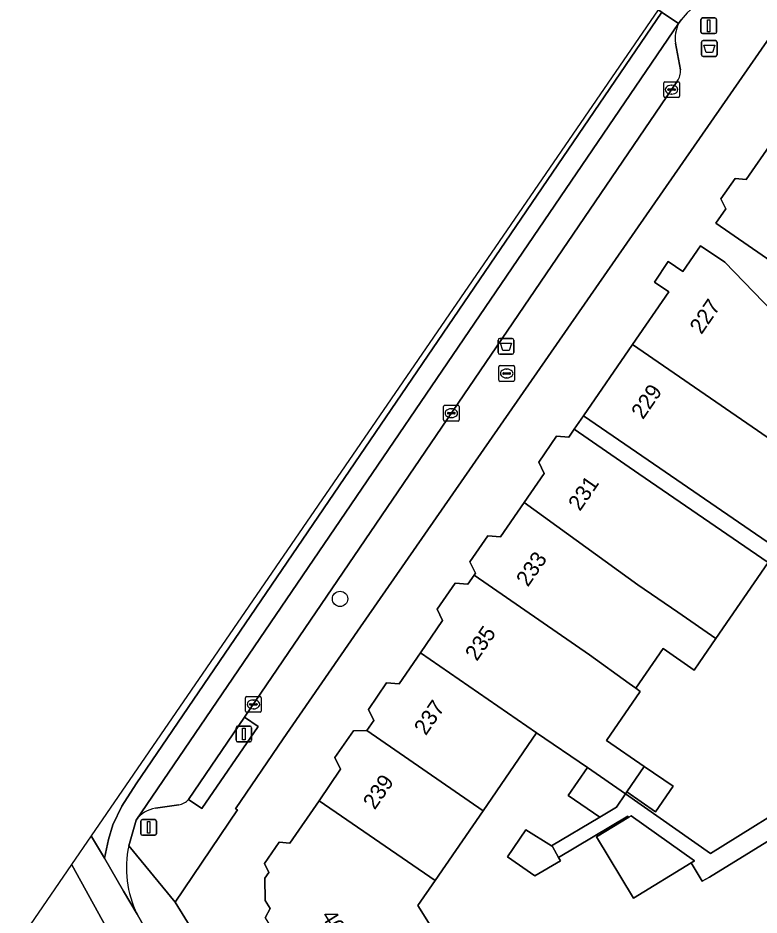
# Model space of a CAD drawing. Extents: x 160023 to 161302, y 384750 to 385707.
# Drawn here: x 160022.6 to 160069.8, y 385314.1 to 385371.2 of the extents above; entities that cross this region are included whole.
import ezdxf

# ---------------------------------------------------------------- set-up
doc = ezdxf.new("R2010")
doc.units = 0
for name, color, linetype in [('IMGEO_Afvalbak', 7, 'Continuous'), ('IMGEO_Boom', 7, 'Continuous'), ('IMGEO_Brandkraan', 7, 'Continuous'), ('IMGEO_Erf', 7, 'Continuous'), ('IMGEO_Fietspad_gesloten', 7, 'Continuous'), ('IMGEO_Kolk', 7, 'Continuous'), ('IMGEO_Lichtmast', 7, 'Continuous'), ('IMGEO_Pand', 7, 'Continuous'), ('IMGEO_Pand_nummerreeks', 7, 'Continuous'), ('IMGEO_Parkeervlak_open', 7, 'Continuous'), ('IMGEO_Rijbaan_lokaal_gesloten', 7, 'Continuous'), ('IMGEO_Rijbaan_lokaal_open', 7, 'Continuous'), ('IMGEO_Rijbaan_regionaal_gesloten', 7, 'Continuous'), ('IMGEO_Verkeersregelinstallatiepaal', 7, 'Continuous'), ('IMGEO_Voetpad_open', 7, 'Continuous')]:
    doc.layers.add(name, color=color, linetype=linetype)

msp = doc.modelspace()

# ---------------------------------------------------------------- linework, layer by layer
at = {"layer": 'IMGEO_Afvalbak'}
for p, q in [((160066.15, 385368.892), (160066.15, 385369.692)), ((160066.15, 385369.692), (160066.15, 385368.892)), ((160066.25, 385369.792), (160067.04, 385369.792)), ((160067.04, 385369.792), (160066.25, 385369.792)), ((160067.14, 385369.692), (160067.14, 385368.892)), ((160067.14, 385368.892), (160067.14, 385369.692)), ((160067.04, 385368.792), (160066.25, 385368.792)), ((160066.25, 385368.792), (160067.04, 385368.792)), ((160053.198, 385349.918), (160053.198, 385350.718)), ((160053.198, 385350.718), (160053.198, 385349.918)), ((160053.298, 385350.818), (160054.088, 385350.818)), ((160054.088, 385350.818), (160053.298, 385350.818)), ((160054.188, 385350.718), (160054.188, 385349.918)), ((160054.188, 385349.918), (160054.188, 385350.718)), ((160054.088, 385349.818), (160053.298, 385349.818)), ((160053.298, 385349.818), (160054.088, 385349.818))]:
    msp.add_line(p, q, dxfattribs=at)
for points in [[(160066.293, 385369.506), (160066.997, 385369.506), (160066.848, 385369.036), (160066.442, 385369.036), (160066.293, 385369.506)], [(160053.341, 385350.532), (160054.045, 385350.532), (160053.896, 385350.062), (160053.49, 385350.062), (160053.341, 385350.532)]]:
    msp.add_lwpolyline(points, dxfattribs=at)
for centre, start, end in [((160066.25, 385369.692), 90, 180), ((160066.25, 385369.692), 90, 180), ((160067.04, 385369.692), 0, 90), ((160067.04, 385369.692), 360, 90), ((160066.25, 385368.892), 180, 270), ((160066.25, 385368.892), 180, 270), ((160067.04, 385368.892), 270, 0), ((160067.04, 385368.892), 270, 0), ((160053.298, 385350.718), 90, 180), ((160053.298, 385350.718), 90, 180), ((160054.088, 385350.718), 0, 90), ((160054.088, 385350.718), 360, 90), ((160053.298, 385349.918), 180, 270), ((160053.298, 385349.918), 180, 270), ((160054.088, 385349.918), 270, 0), ((160054.088, 385349.918), 270, 0)]:
    msp.add_arc(centre, 0.1, start, end, dxfattribs=at)
at = {"layer": 'IMGEO_Boom'}
msp.add_circle((160043.126, 385334.233), 0.489, dxfattribs=at)
at = {"layer": 'IMGEO_Brandkraan'}
for p, q in [((160053.241, 385348.164), (160053.241, 385349.016)), ((160053.316, 385349.09), (160054.168, 385349.09)), ((160054.242, 385349.016), (160054.242, 385348.164)), ((160053.5, 385348.584), (160053.5, 385348.596)), ((160053.938, 385348.547), (160053.54, 385348.547)), ((160053.543, 385348.633), (160053.941, 385348.633)), ((160053.729, 385348.87), (160053.754, 385348.87)), ((160053.984, 385348.596), (160053.984, 385348.584)), ((160054.168, 385348.09), (160053.316, 385348.09)), ((160053.752, 385348.31), (160053.727, 385348.31))]:
    msp.add_line(p, q, dxfattribs=at)
for points in [[(160053.241, 385348.164), (160053.241, 385349.016)], [(160053.316, 385349.09), (160054.168, 385349.09)], [(160054.242, 385349.016), (160054.242, 385348.164)], [(160054.168, 385348.09), (160053.316, 385348.09)]]:
    msp.add_lwpolyline(points, dxfattribs=at)
for centre, radius, start, end in [((160053.318, 385349.014), 0.0765, 91.552, 178.448), ((160053.318, 385349.014), 0.0765, 91.552, 178.448), ((160054.166, 385349.014), 0.0765, 1.552, 88.448), ((160054.166, 385349.014), 0.0765, 1.552, 88.448), ((160053.54, 385348.593), 0.0403, 85.8775, 175.7526), ((160053.537, 385348.583), 0.0366, 178.938, 274.7102), ((160053.941, 385348.59), 0.043, 264.8664, 352.4533), ((160053.945, 385348.595), 0.0386, 1.7309, 96.639), ((160053.318, 385348.166), 0.0765, 181.552, 268.448), ((160053.318, 385348.166), 0.0765, 181.552, 268.448), ((160054.166, 385348.166), 0.0765, 271.552, 358.448), ((160054.166, 385348.166), 0.0765, 271.552, 358.448)]:
    msp.add_arc(centre, radius, start, end, dxfattribs=at)
for centre, major_axis, ratio, start_param, end_param in [((160053.728, 385348.59), (-0.387, 0.002), 0.722429, 4.712389, 7.853982), ((160053.753, 385348.59), (-0.39, 0.002), 0.717154, 1.570796, 4.712389)]:
    msp.add_ellipse(centre, major_axis=major_axis, ratio=ratio, start_param=start_param, end_param=end_param, dxfattribs=at)
at = {"layer": 'IMGEO_Erf'}
for points in [[(160071.027, 385370.783), (160044.24, 385332.184), (160039.513, 385325.31), (160036.466, 385320.863), (160036.589, 385320.788), (160032.616, 385314.905), (160038.148, 385305.982), (160037.936, 385305.85), (160040.989, 385300.92), (160040.82, 385300.82), (160046.575, 385291.663), (160050.286, 385285.709), (160050.755, 385284.956), (160071.649, 385251.538)], [(160071.173, 385355.328), (160067.053, 385358.162), (160067.689, 385359.086), (160067.39, 385359.713), (160068.285, 385361.013), (160068.998, 385360.957), (160070.662, 385363.376)], [(160038.364, 385313.922), (160038.676, 385314.504), (160038.362, 385315.011), (160038.339, 385316.435), (160038.595, 385316.807), (160038.321, 385317.381), (160039.25, 385318.732), (160039.931, 385318.678), (160041.788, 385321.377), (160043.165, 385323.378), (160042.805, 385324.133), (160043.974, 385325.832), (160044.834, 385325.842), (160045.271, 385326.478), (160044.932, 385327.191), (160046.095, 385328.882), (160046.882, 385328.82), (160048.242, 385330.796), (160049.661, 385332.858), (160049.322, 385333.568), (160050.463, 385335.226), (160051.262, 385335.163), (160051.661, 385335.742), (160051.744, 385335.863), (160051.399, 385336.587), (160052.545, 385338.252), (160053.354, 385338.188), (160054.852, 385340.366), (160056.123, 385342.214), (160055.778, 385342.939), (160056.923, 385344.603), (160057.702, 385344.542), (160058.043, 385345.037), (160058.636, 385345.901), (160061.755, 385350.435), (160064.066, 385353.794), (160063.16, 385354.418), (160064.023, 385355.726), (160064.953, 385355.085), (160066.087, 385356.732), (160067.626, 385355.673), (160079.267, 385343.639)], [(160074.623, 385321.403), (160066.649, 385316.515), (160066.202, 385316.241), (160065.482, 385317.415), (160061.817, 385315.167), (160059.466, 385319.068), (160061.52, 385320.328), (160061.447, 385320.382), (160057.04, 385317.763), (160057.164, 385317.535), (160055.536, 385316.6), (160053.788, 385317.805), (160054.969, 385319.521), (160056.599, 385318.501), (160059.668, 385320.325), (160057.663, 385321.709), (160058.882, 385323.481), (160055.647, 385325.694), (160052.239, 385320.739), (160049.176, 385316.287), (160048.085, 385314.701), (160049.288, 385312.761)]]:
    msp.add_lwpolyline(points, dxfattribs=at)
msp.add_lwpolyline([(160074.014, 385330.761), (160070.393, 385336.541), (160067.07, 385331.71), (160066.008, 385330.166), (160065.688, 385329.701), (160063.701, 385331.067), (160061.962, 385328.538), (160062.243, 385328.334), (160060.097, 385325.214), (160062.498, 385323.562), (160064.341, 385322.294), (160063.223, 385320.668), (160061.387, 385321.931), (160061.311, 385321.819), (160066.718, 385318.006), (160079.412, 385325.901), (160079.412, 385327.14), (160078.89, 385327.49)], close=True, dxfattribs=at)
at = {"layer": 'IMGEO_Fietspad_gesloten'}
msp.add_lwpolyline([(160026.031, 385317.314), (160026.044, 385317.29), (160028.006, 385313.738), (160028.321, 385313.156), (160030.444, 385309.783), (160032.543, 385306.417), (160061.871, 385259.541), (160067.835, 385250), (160085.578, 385221.627), (160124.152, 385160.161), (160150.574, 385117.95), (160168.154, 385089.798), (160170.064, 385090.861), (160169.92, 385091.091), (160127.678, 385158.489), (160123.778, 385164.743), (160087.491, 385222.641), (160070.35, 385250), (160030.703, 385313.283), (160030.2, 385314.143), (160029.339, 385315.616), (160028.117, 385317.706), (160027.3, 385319.103), (160027.281, 385319.136)], close=True, dxfattribs=at)
at = {"layer": 'IMGEO_Kolk'}
for p, q in [((160063.741, 385366.248), (160063.741, 385367.1)), ((160063.816, 385367.174), (160064.668, 385367.174)), ((160064.043, 385366.717), (160064.441, 385366.717)), ((160064.229, 385366.954), (160064.254, 385366.954)), ((160064.742, 385367.1), (160064.742, 385366.248)), ((160064.668, 385366.174), (160063.816, 385366.174)), ((160064, 385366.668), (160064, 385366.68)), ((160064.438, 385366.631), (160064.04, 385366.631)), ((160064.252, 385366.394), (160064.227, 385366.394)), ((160064.484, 385366.68), (160064.484, 385366.668)), ((160049.715, 385345.636), (160049.715, 385346.488)), ((160049.79, 385346.562), (160050.642, 385346.562)), ((160050.203, 385346.342), (160050.228, 385346.342)), ((160050.716, 385346.488), (160050.716, 385345.636)), ((160050.642, 385345.562), (160049.79, 385345.562)), ((160049.974, 385346.056), (160049.974, 385346.068)), ((160050.412, 385346.019), (160050.014, 385346.019)), ((160050.017, 385346.105), (160050.415, 385346.105)), ((160050.226, 385345.782), (160050.201, 385345.782)), ((160050.458, 385346.068), (160050.458, 385346.056)), ((160037.109, 385327.083), (160037.109, 385327.935)), ((160037.184, 385328.009), (160038.036, 385328.009)), ((160038.11, 385327.935), (160038.11, 385327.083)), ((160037.368, 385327.503), (160037.368, 385327.515)), ((160037.806, 385327.466), (160037.408, 385327.466)), ((160037.411, 385327.552), (160037.809, 385327.552)), ((160037.597, 385327.789), (160037.622, 385327.789)), ((160037.852, 385327.515), (160037.852, 385327.503)), ((160038.036, 385327.009), (160037.184, 385327.009)), ((160037.62, 385327.229), (160037.595, 385327.229))]:
    msp.add_line(p, q, dxfattribs=at)
for points in [[(160063.741, 385366.248), (160063.741, 385367.1)], [(160063.816, 385367.174), (160064.668, 385367.174)], [(160064.742, 385367.1), (160064.742, 385366.248)], [(160064.668, 385366.174), (160063.816, 385366.174)], [(160049.715, 385345.636), (160049.715, 385346.488)], [(160049.79, 385346.562), (160050.642, 385346.562)], [(160050.716, 385346.488), (160050.716, 385345.636)], [(160050.642, 385345.562), (160049.79, 385345.562)], [(160037.109, 385327.083), (160037.109, 385327.935)], [(160037.184, 385328.009), (160038.036, 385328.009)], [(160038.11, 385327.935), (160038.11, 385327.083)], [(160038.036, 385327.009), (160037.184, 385327.009)]]:
    msp.add_lwpolyline(points, dxfattribs=at)
for centre, radius, start, end in [((160063.818, 385367.098), 0.0765, 91.552, 178.448), ((160063.818, 385367.098), 0.0765, 91.552, 178.448), ((160064.04, 385366.677), 0.0403, 85.8775, 175.7526), ((160064.445, 385366.679), 0.0386, 1.7309, 96.639), ((160064.666, 385367.098), 0.0765, 1.552, 88.448), ((160064.666, 385367.098), 0.0765, 1.552, 88.448), ((160063.818, 385366.25), 0.0765, 181.552, 268.448), ((160063.818, 385366.25), 0.0765, 181.552, 268.448), ((160064.037, 385366.667), 0.0366, 178.938, 274.7102), ((160064.441, 385366.674), 0.043, 264.8664, 352.4533), ((160064.666, 385366.25), 0.0765, 271.552, 358.448), ((160064.666, 385366.25), 0.0765, 271.552, 358.448), ((160049.792, 385346.486), 0.0765, 91.552, 178.448), ((160049.792, 385346.486), 0.0765, 91.552, 178.448), ((160050.64, 385346.486), 0.0765, 1.552, 88.448), ((160050.64, 385346.486), 0.0765, 1.552, 88.448), ((160049.792, 385345.638), 0.0765, 181.552, 268.448), ((160049.792, 385345.638), 0.0765, 181.552, 268.448), ((160050.014, 385346.065), 0.0403, 85.8775, 175.7526), ((160050.011, 385346.055), 0.0366, 178.938, 274.7102), ((160050.415, 385346.062), 0.043, 264.8664, 352.4533), ((160050.419, 385346.067), 0.0386, 1.7309, 96.639), ((160050.64, 385345.638), 0.0765, 271.552, 358.448), ((160050.64, 385345.638), 0.0765, 271.552, 358.448), ((160037.186, 385327.933), 0.0765, 91.552, 178.448), ((160037.186, 385327.933), 0.0765, 91.552, 178.448), ((160038.034, 385327.933), 0.0765, 1.552, 88.448), ((160038.034, 385327.933), 0.0765, 1.552, 88.448), ((160037.408, 385327.512), 0.0403, 85.8775, 175.7526), ((160037.405, 385327.502), 0.0366, 178.938, 274.7102), ((160037.809, 385327.509), 0.043, 264.8664, 352.4533), ((160037.813, 385327.514), 0.0386, 1.7309, 96.639), ((160037.186, 385327.085), 0.0765, 181.552, 268.448), ((160037.186, 385327.085), 0.0765, 181.552, 268.448), ((160038.034, 385327.085), 0.0765, 271.552, 358.448), ((160038.034, 385327.085), 0.0765, 271.552, 358.448)]:
    msp.add_arc(centre, radius, start, end, dxfattribs=at)
for centre, major_axis, ratio, start_param, end_param in [((160064.228, 385366.674), (-0.387, 0.002), 0.722429, 4.712389, 7.853982), ((160064.253, 385366.674), (-0.39, 0.002), 0.717154, 1.570796, 4.712389), ((160050.202, 385346.062), (-0.387, 0.002), 0.722429, 4.712389, 7.853982), ((160050.227, 385346.062), (-0.39, 0.002), 0.717154, 1.570796, 4.712389), ((160037.596, 385327.509), (-0.387, 0.002), 0.722429, 4.712389, 7.853982), ((160037.621, 385327.509), (-0.39, 0.002), 0.717154, 1.570796, 4.712389)]:
    msp.add_ellipse(centre, major_axis=major_axis, ratio=ratio, start_param=start_param, end_param=end_param, dxfattribs=at)
at = {"layer": 'IMGEO_Lichtmast'}
for p, q in [((160066.117, 385370.34), (160066.117, 385371.14)), ((160066.117, 385371.14), (160066.117, 385370.34)), ((160066.217, 385371.24), (160067.007, 385371.24)), ((160067.007, 385371.24), (160066.217, 385371.24)), ((160067.107, 385371.14), (160067.107, 385370.34)), ((160067.107, 385370.34), (160067.107, 385371.14)), ((160067.007, 385370.24), (160066.217, 385370.24)), ((160066.217, 385370.24), (160067.007, 385370.24)), ((160036.603, 385326.125), (160037.393, 385326.125)), ((160037.393, 385326.125), (160036.603, 385326.125)), ((160036.503, 385325.225), (160036.503, 385326.025)), ((160036.503, 385326.025), (160036.503, 385325.225)), ((160037.493, 385326.025), (160037.493, 385325.225)), ((160037.493, 385325.225), (160037.493, 385326.025)), ((160037.393, 385325.125), (160036.603, 385325.125)), ((160036.603, 385325.125), (160037.393, 385325.125))]:
    msp.add_line(p, q, dxfattribs=at)
for points in [[(160066.537, 385371.115), (160066.687, 385371.115), (160066.687, 385370.365), (160066.537, 385370.365), (160066.537, 385371.115)], [(160036.923, 385326), (160037.073, 385326), (160037.073, 385325.25), (160036.923, 385325.25), (160036.923, 385326)]]:
    msp.add_lwpolyline(points, dxfattribs=at)
for centre, start, end in [((160066.217, 385371.14), 90, 180), ((160066.217, 385371.14), 90, 180), ((160067.007, 385371.14), 0, 90), ((160067.007, 385371.14), 360, 90), ((160066.217, 385370.34), 180, 270), ((160066.217, 385370.34), 180, 270), ((160067.007, 385370.34), 270, 0), ((160067.007, 385370.34), 270, 0), ((160036.603, 385326.025), 90, 180), ((160036.603, 385326.025), 90, 180), ((160037.393, 385326.025), 0, 90), ((160037.393, 385326.025), 360, 90), ((160036.603, 385325.225), 180, 270), ((160036.603, 385325.225), 180, 270), ((160037.393, 385325.225), 270, 0), ((160037.393, 385325.225), 270, 0)]:
    msp.add_arc(centre, 0.1, start, end, dxfattribs=at)
at = {"layer": 'IMGEO_Pand'}
for points in [[(160068.998, 385360.957), (160068.285, 385361.013), (160067.39, 385359.713), (160067.689, 385359.086), (160067.053, 385358.162), (160071.173, 385355.328), (160074.43, 385353.086), (160076.272, 385355.763), (160080.744, 385352.686), (160081.512, 385353.802), (160082.496, 385355.232), (160070.662, 385363.376)], [(160067.626, 385355.673), (160066.087, 385356.732), (160064.953, 385355.085), (160064.023, 385355.726), (160063.16, 385354.418), (160064.066, 385353.794), (160061.755, 385350.435), (160075.631, 385340.89), (160076.516, 385339.641), (160082.452, 385330.867), (160085.987, 385336.004), (160086.261, 385336.403), (160086.233, 385336.432), (160079.267, 385343.639)], [(160061.755, 385350.435), (160058.636, 385345.901), (160062.756, 385343.067), (160071.409, 385337.114), (160073.695, 385335.541), (160076.433, 385339.52), (160076.516, 385339.641), (160075.631, 385340.89)], [(160064.647, 385333.377), (160067.07, 385331.71), (160070.393, 385336.541), (160062.163, 385342.203), (160058.043, 385345.037), (160057.702, 385344.542), (160056.923, 385344.603), (160055.778, 385342.939), (160056.123, 385342.214), (160054.852, 385340.366), (160062.091, 385335.135)], [(160062.091, 385335.135), (160054.852, 385340.366), (160053.354, 385338.188), (160052.545, 385338.252), (160051.399, 385336.587), (160051.744, 385335.863), (160051.661, 385335.742), (160059.019, 385330.672), (160061.532, 385328.85), (160061.962, 385328.538), (160063.701, 385331.067), (160065.688, 385329.701), (160066.008, 385330.166), (160067.07, 385331.71), (160064.647, 385333.377)], [(160059.019, 385330.672), (160051.661, 385335.742), (160051.262, 385335.163), (160050.463, 385335.226), (160049.322, 385333.568), (160049.661, 385332.858), (160048.242, 385330.796), (160055.647, 385325.694), (160058.882, 385323.481), (160061.311, 385321.819), (160061.387, 385321.931), (160062.498, 385323.562), (160060.097, 385325.214), (160062.243, 385328.334), (160061.962, 385328.538), (160061.532, 385328.85)], [(160044.834, 385325.842), (160052.239, 385320.739), (160055.647, 385325.694), (160048.242, 385330.796), (160046.882, 385328.82), (160046.095, 385328.882), (160044.932, 385327.191), (160045.271, 385326.478)], [(160041.788, 385321.377), (160049.176, 385316.287), (160052.239, 385320.739), (160044.834, 385325.842), (160043.974, 385325.832), (160042.805, 385324.133), (160043.165, 385323.378)], [(160061.311, 385321.819), (160058.882, 385323.481), (160057.663, 385321.709), (160059.668, 385320.325), (160060.725, 385320.959)], [(160062.498, 385323.562), (160061.387, 385321.931), (160063.223, 385320.668), (160064.341, 385322.294)], [(160042.71, 385307.971), (160050.317, 385312.681), (160049.995, 385313.2), (160049.288, 385312.761), (160048.085, 385314.701), (160049.176, 385316.287), (160041.788, 385321.377), (160039.931, 385318.678), (160039.25, 385318.732), (160038.321, 385317.381), (160038.595, 385316.807), (160038.339, 385316.435), (160038.362, 385315.011), (160038.676, 385314.504), (160038.364, 385313.922), (160039.593, 385311.941), (160040.342, 385311.766), (160040.632, 385311.3), (160040.258, 385310.602), (160041.348, 385308.844), (160042.152, 385308.87)], [(160065.482, 385317.415), (160065.71, 385317.555), (160061.663, 385320.416), (160061.52, 385320.328), (160059.466, 385319.068), (160061.817, 385315.167)], [(160057.04, 385317.763), (160056.661, 385318.462), (160056.599, 385318.501), (160054.969, 385319.521), (160053.788, 385317.805), (160055.536, 385316.6), (160057.164, 385317.535)]]:
    msp.add_lwpolyline(points, close=True, dxfattribs=at)
at = {"layer": 'IMGEO_Parkeervlak_open'}
for points in [[(160064.691, 385370.881), (160030.138, 385320.131)], [(160064.804, 385367.927), (160064.502, 385369.624)], [(160033.48, 385321.459), (160037.043, 385326.7), (160064.614, 385367.23)], [(160031.366, 385320.895), (160032.86, 385321.122)]]:
    msp.add_lwpolyline(points, dxfattribs=at)
for centre, radius, start, end in [((160066.553, 385369.958), 2.078, 153.6431, 189.2552), ((160063.85, 385367.813), 0.961, 322.6729, 6.8308), ((160032.74, 385322.081), 0.967, 277.1227, 319.9297), ((160031.669, 385319.039), 1.881, 99.2743, 144.5014)]:
    msp.add_arc(centre, radius, start, end, dxfattribs=at)
at = {"layer": 'IMGEO_Rijbaan_lokaal_gesloten'}
msp.add_lwpolyline([(160027.281, 385319.136), (160027.3, 385319.103), (160028.117, 385317.706), (160028.37, 385318.91), (160028.65, 385319.84), (160029.23, 385321.02), (160030.15, 385322.46), (160063.617, 385371.61), (160063.394, 385371.761), (160050.807, 385353.419)], close=True, dxfattribs=at)
for points in [[(160064.691, 385370.881), (160063.639, 385371.595), (160063.617, 385371.61), (160030.15, 385322.46), (160029.23, 385321.02), (160028.65, 385319.84), (160028.37, 385318.91), (160028.117, 385317.706), (160029.339, 385315.616), (160030.2, 385314.143)], [(160029.665, 385318.496), (160030.138, 385320.131), (160064.691, 385370.881)]]:
    msp.add_lwpolyline(points, dxfattribs=at)
msp.add_arc((160036.231, 385317.094), 6.714, 167.9439, 206.0696, dxfattribs=at)
at = {"layer": 'IMGEO_Rijbaan_lokaal_open'}
msp.add_lwpolyline([(160063.394, 385371.761), (160063.617, 385371.61), (160063.639, 385371.595), (160064.691, 385370.881), (160064.848, 385371.116)], dxfattribs=at)
msp.add_arc((160069.372, 385367.566), 5.751, 52.0889, 141.8775, dxfattribs=at)
at = {"layer": 'IMGEO_Rijbaan_regionaal_gesloten'}
msp.add_lwpolyline([(160028.321, 385313.156), (160028.006, 385313.738), (160026.044, 385317.29), (160026.031, 385317.314), (160022.611, 385312.331), (160033.754, 385294.437)], dxfattribs=at)
at = {"layer": 'IMGEO_Verkeersregelinstallatiepaal'}
for p, q in [((160030.439, 385319.274), (160030.439, 385320.074)), ((160030.439, 385320.074), (160030.439, 385319.274)), ((160030.539, 385320.174), (160031.329, 385320.174)), ((160031.329, 385320.174), (160030.539, 385320.174)), ((160031.429, 385320.074), (160031.429, 385319.274)), ((160031.429, 385319.274), (160031.429, 385320.074)), ((160031.329, 385319.174), (160030.539, 385319.174)), ((160030.539, 385319.174), (160031.329, 385319.174))]:
    msp.add_line(p, q, dxfattribs=at)
msp.add_lwpolyline([(160030.859, 385320.049), (160031.009, 385320.049), (160031.009, 385319.299), (160030.859, 385319.299), (160030.859, 385320.049)], dxfattribs=at)
for centre, start, end in [((160030.539, 385320.074), 90, 180), ((160030.539, 385320.074), 90, 180), ((160031.329, 385320.074), 0, 90), ((160031.329, 385320.074), 360, 90), ((160030.539, 385319.274), 180, 270), ((160030.539, 385319.274), 180, 270), ((160031.329, 385319.274), 270, 0), ((160031.329, 385319.274), 270, 0)]:
    msp.add_arc(centre, 0.1, start, end, dxfattribs=at)
at = {"layer": 'IMGEO_Voetpad_open'}
for points in [[(160030.138, 385320.131), (160029.665, 385318.496), (160032.616, 385314.905), (160036.589, 385320.788), (160036.466, 385320.863), (160039.513, 385325.31), (160044.24, 385332.184), (160071.027, 385370.783)], [(160064.848, 385371.116), (160064.691, 385370.881)], [(160064.502, 385369.624), (160064.804, 385367.927)], [(160064.614, 385367.23), (160037.043, 385326.7), (160037.909, 385326.109), (160034.334, 385320.889), (160033.48, 385321.459)], [(160071.409, 385337.114), (160062.756, 385343.067), (160058.636, 385345.901), (160058.043, 385345.037), (160062.163, 385342.203), (160070.393, 385336.541)], [(160079.412, 385325.901), (160066.718, 385318.006), (160061.311, 385321.819), (160060.725, 385320.959), (160059.668, 385320.325), (160056.599, 385318.501), (160056.661, 385318.462), (160057.04, 385317.763), (160061.447, 385320.382), (160061.52, 385320.328), (160061.663, 385320.416), (160065.71, 385317.555), (160065.482, 385317.415), (160066.202, 385316.241), (160066.649, 385316.515), (160074.623, 385321.403)], [(160032.86, 385321.122), (160031.366, 385320.895)], [(160032.616, 385314.905), (160029.665, 385318.496)], [(160103.458, 385200.92), (160089.292, 385223.094), (160085.619, 385228.915), (160085.88, 385229.102), (160078.493, 385240.928), (160078.326, 385240.862), (160075.929, 385244.686), (160076.049, 385244.741), (160072.82, 385250), (160071.814, 385251.639), (160071.649, 385251.538), (160050.755, 385284.956), (160050.286, 385285.709), (160046.575, 385291.663), (160040.82, 385300.82), (160040.989, 385300.92), (160037.936, 385305.85), (160038.148, 385305.982), (160032.616, 385314.905)], [(160030.2, 385314.143), (160030.703, 385313.283), (160070.35, 385250), (160087.491, 385222.641), (160123.778, 385164.743)]]:
    msp.add_lwpolyline(points, dxfattribs=at)
msp.add_lwpolyline([(160037.043, 385326.7), (160033.48, 385321.459), (160034.334, 385320.889), (160037.909, 385326.109)], close=True, dxfattribs=at)
for centre, radius, start, end in [((160069.372, 385367.566), 5.751, 52.0889, 141.8775), ((160066.553, 385369.958), 2.078, 153.6431, 189.2552), ((160063.85, 385367.813), 0.961, 322.6729, 6.8308), ((160032.74, 385322.081), 0.967, 277.1227, 319.9297), ((160031.669, 385319.039), 1.881, 99.2743, 144.5014), ((160036.231, 385317.094), 6.714, 167.9439, 206.0696)]:
    msp.add_arc(centre, radius, start, end, dxfattribs=at)

# ---------------------------------------------------------------- texts
at = {"layer": 'IMGEO_Pand_nummerreeks'}
for s, rotation, p in [('227', 55.4738, (160066.145, 385351.03)), ('229', 55.4738, (160062.42, 385345.614)), ('231', 55.5102, (160058.405, 385339.771)), ('233', 55.5082, (160055.09, 385334.946)), ('235', 55.5082, (160051.839, 385330.214)), ('237', 55.5102, (160048.588, 385325.482)), ('239', 55.5102, (160045.337, 385320.75)), ('402', 301.8947, (160041.897, 385314.037))]:
    msp.add_text(s, height=1, rotation=rotation, dxfattribs=at).set_placement(p)

doc.saveas('drawing.dxf')
